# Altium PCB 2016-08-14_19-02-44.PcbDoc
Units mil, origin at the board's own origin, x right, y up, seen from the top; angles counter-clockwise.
Board outline 1900 x 2200 mil, 4 copper layers (Top Layer, MidLayer1, MidLayer2, Bottom Layer); 19 components, 10 nets, 41 pads, 48 vias.
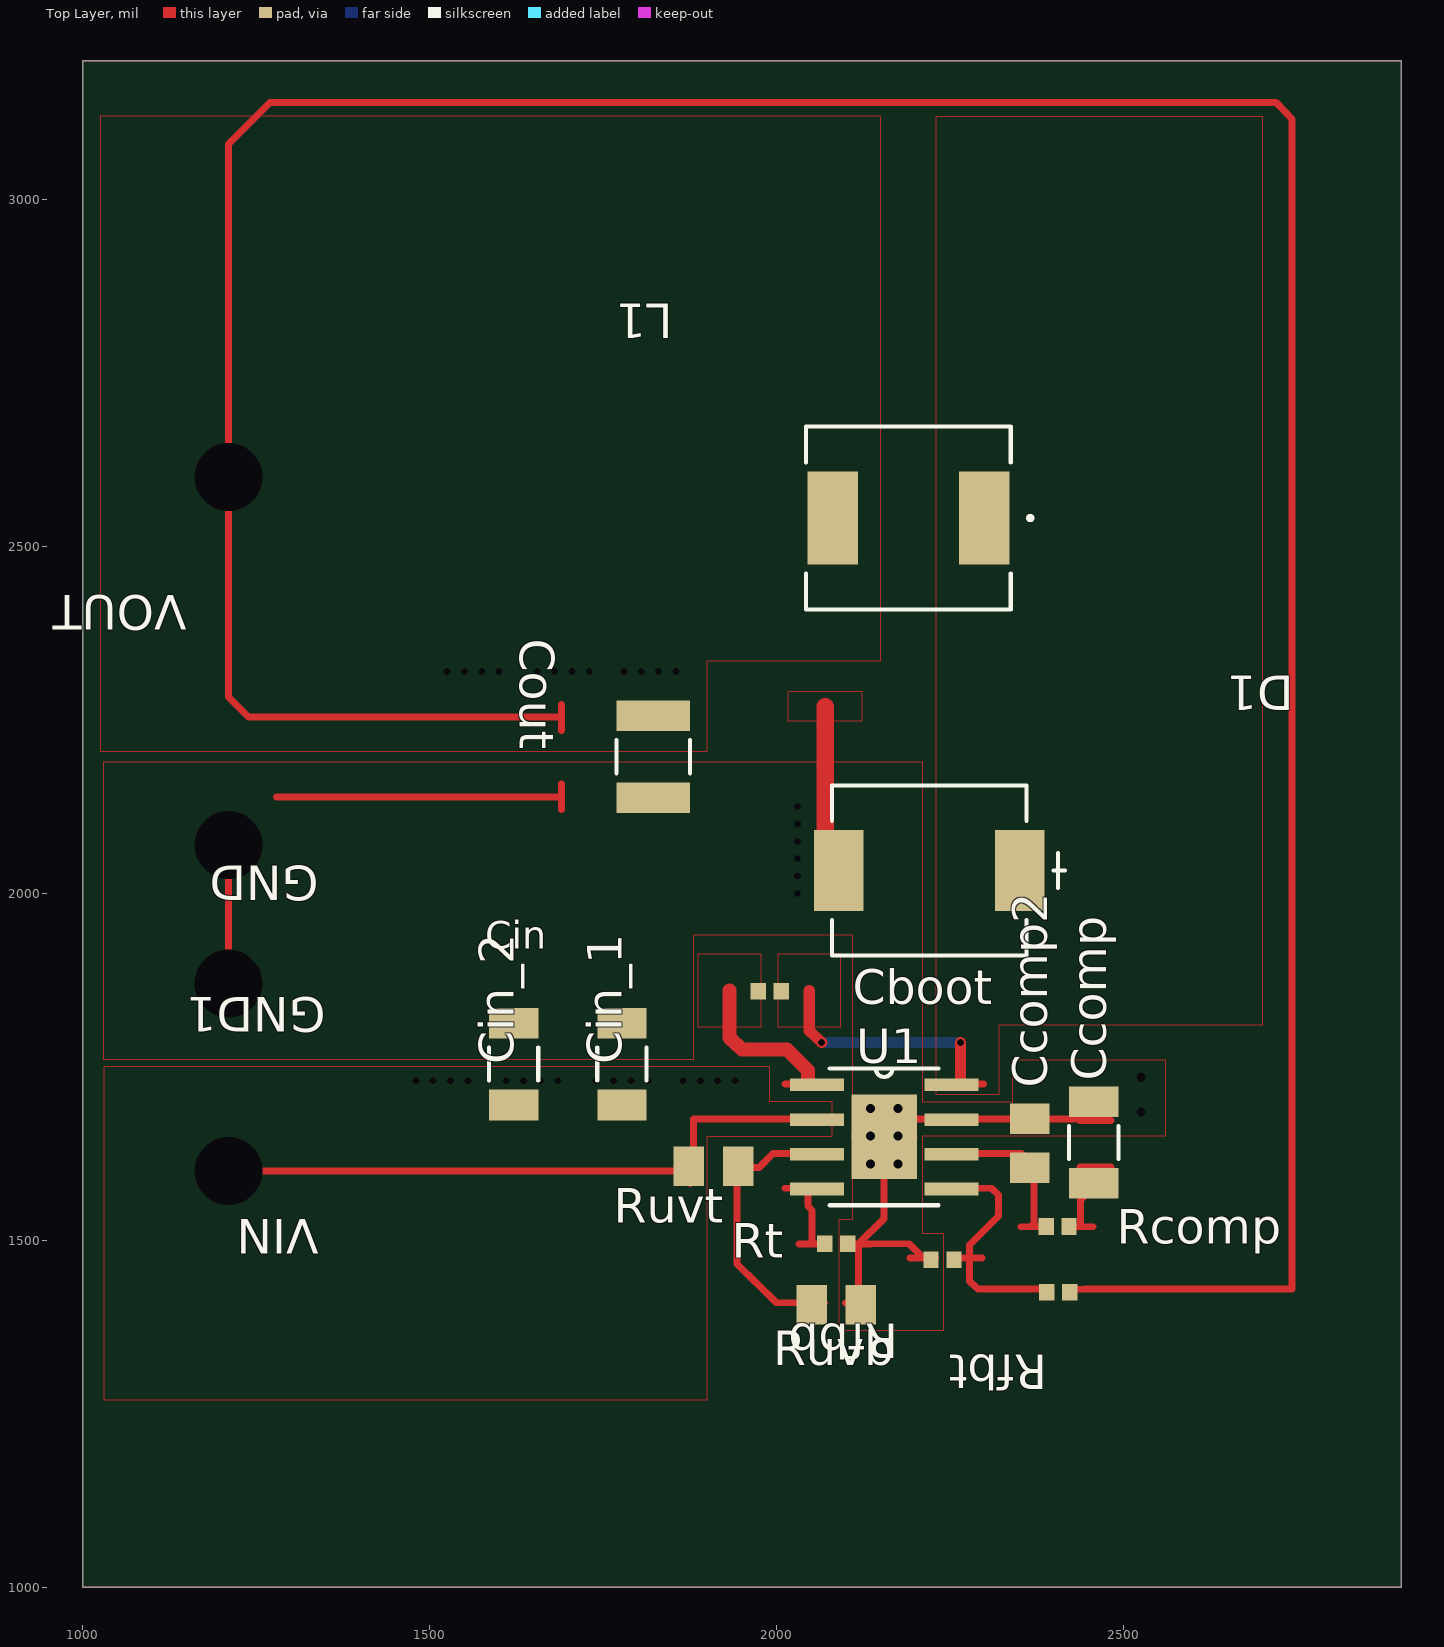
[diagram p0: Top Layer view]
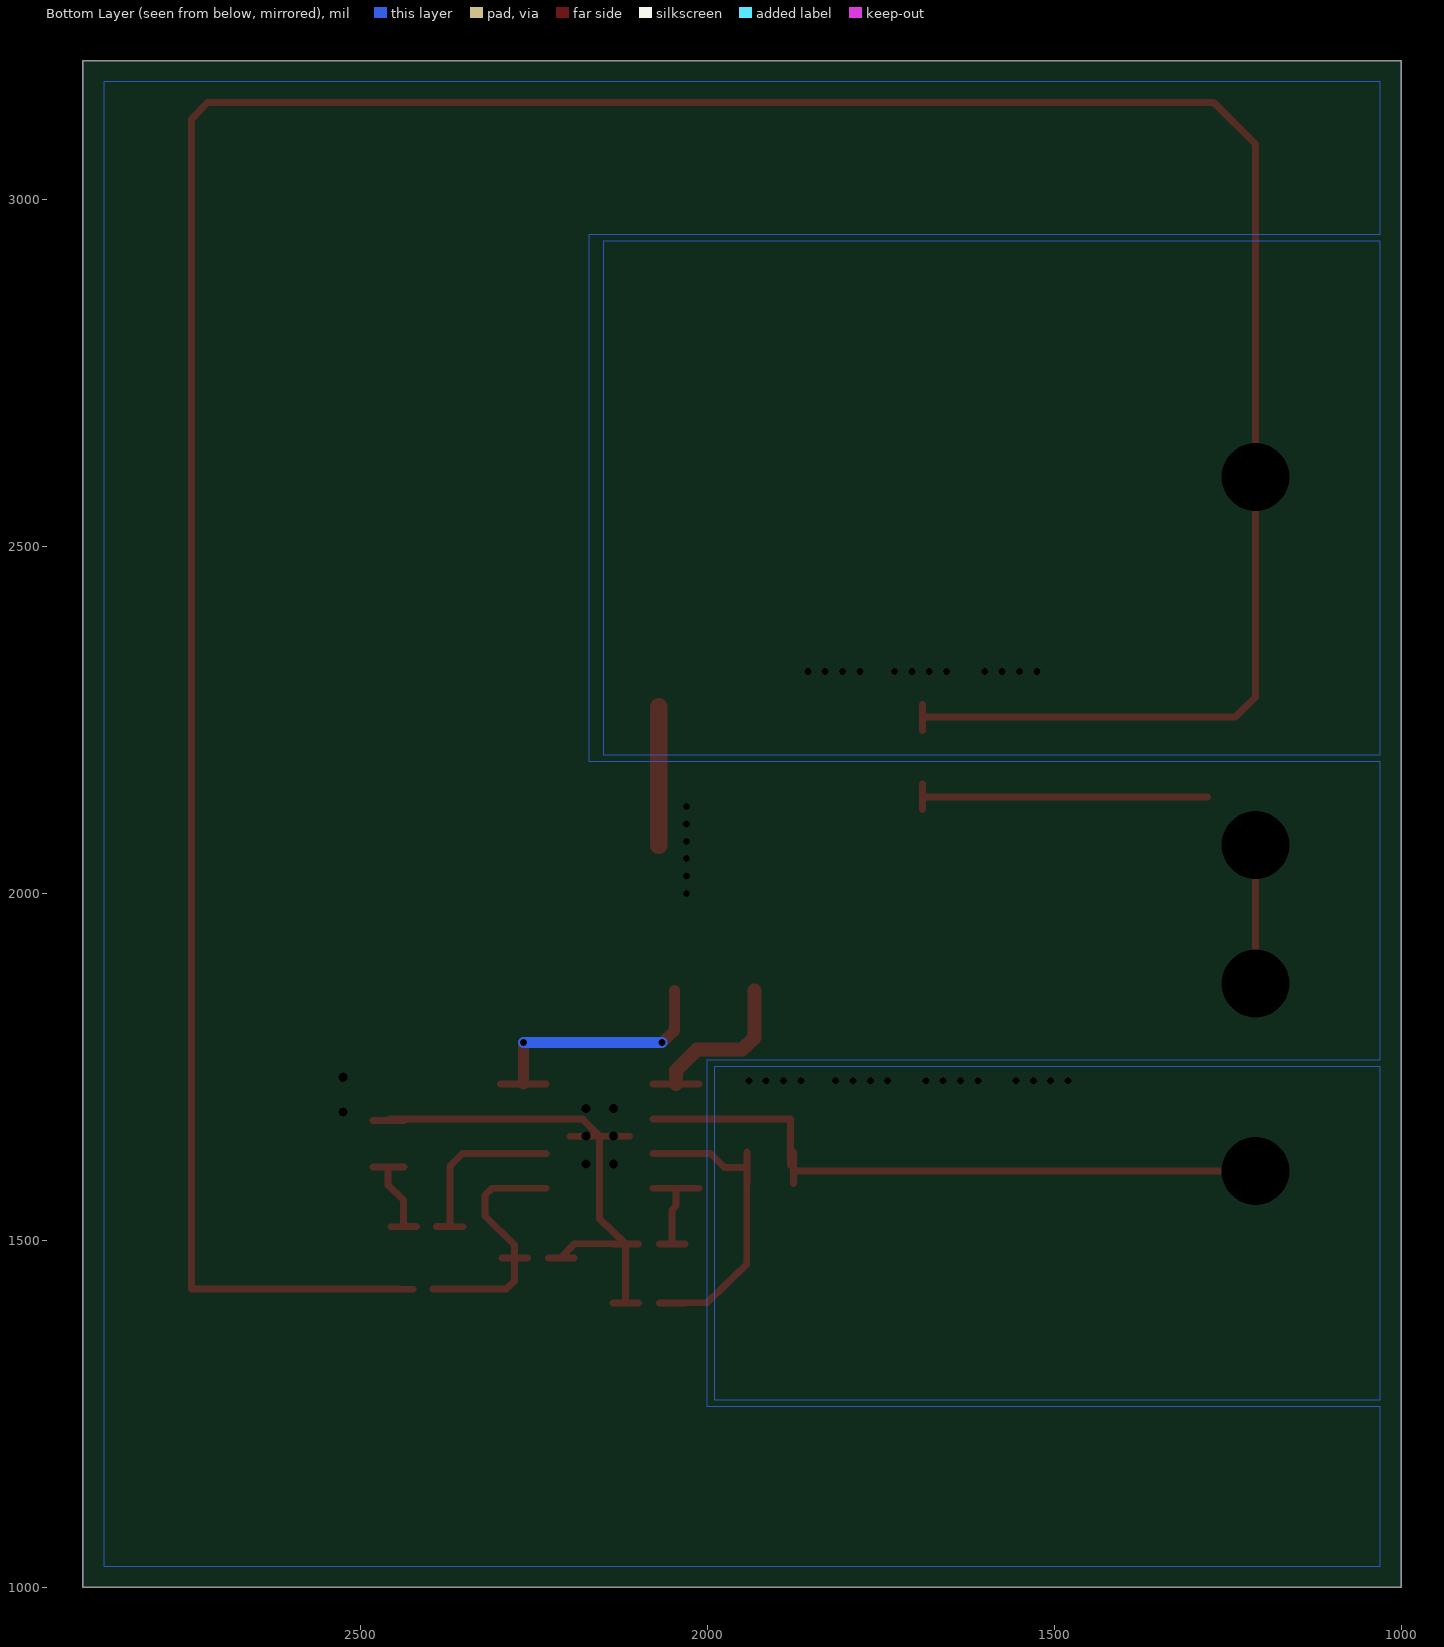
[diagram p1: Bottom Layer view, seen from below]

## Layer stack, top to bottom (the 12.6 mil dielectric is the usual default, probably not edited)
Top Layer: signal copper 1.4
Dielectric: core 12.6, FR-4, Dk 4.8
MidLayer1: signal copper 1.4
Dielectric: prepreg 12.6, FR-4, Dk 4.8
MidLayer2: signal copper 1.4
Dielectric: core 12.6, FR-4, Dk 4.8
Bottom Layer: signal copper 1.4

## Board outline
1000,1000 2900,1000 2900,3200 1000,3200

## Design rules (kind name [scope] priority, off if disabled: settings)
PlaneConnect [All] p0: scope1count=1 scope1_0_kind=Board scope1_0_value=Board scope2count=1 scope2_0_kind=Board scope2_0_value=Board commentlength=0 planeconnectstyle=Direct reliefexpansion=20 reliefentries=4 reliefconductorwidth=10 reliefairgap=10
PlaneConnect [All] p1: planeconnectstyle=Direct reliefexpansion=20 reliefentries=4 reliefconductorwidth=10 reliefairgap=10
PolygonConnect [All] p0: scope1count=1 scope1_0_kind=Board scope1_0_value=Board scope2count=1 scope2_0_kind=Board scope2_0_value=Board commentlength=0 connectstyle=Direct reliefconductorwidth=10 reliefentries=4 polygonreliefangle="90 Angle"
PolygonConnect [All] p1: connectstyle=Direct reliefconductorwidth=10 reliefentries=4 polygonreliefangle="90 Angle"

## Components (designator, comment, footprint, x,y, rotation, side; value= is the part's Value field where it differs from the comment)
Cboot "" 0402 1990,1859 r0 top
Ccomp "" 1206 2457,1641 r90 top
Ccomp2 "" 0805 2365,1640 r90 top
Cin_1 "" 1206 1777,1754 r90 top
Cin_2 "" 1206 1621,1754 r90 top
Cout "" 1210_280 1822,2197 r270 top
D1 "" SMC 2220,2033 r180 top
GND "" TP-1502 1209,2068 r180 top
GND1 "" TP-1502 1209,1870 r180 top
L1 "" SRP6540 2190,2541 r180 top
Rcomp "" 0402 2405,1520 r0 top
Rfbb "" 0402 2239,1472 r180 top
Rfbt "" 0402 2406,1425 r180 top
Rt "" 0402 2086,1495 r0 top
Ruvb "" 0805 2086,1407 r0 top
Ruvt "" 0805 1909,1607 r0 top
U1 "" R-PDSO-G8 2155,1649 r0 top
VIN "" TP-1502 1209,1599 r180 top
VOUT "" TP-1502 1209,2599 r180 top

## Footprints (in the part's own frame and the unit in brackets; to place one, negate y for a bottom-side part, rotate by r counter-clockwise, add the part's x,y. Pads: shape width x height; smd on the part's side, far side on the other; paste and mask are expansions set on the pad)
0402 [mil]
  rect 22x24 smd: 1(-16.5,0) 2(16.5,0)
0805 [mil]
  rect 44x57 smd: 1(-35.5,0) 2(35.5,0)
1206 [mil]
  rect 44x71 smd: 1(-59,0) 2(59,0)
  silkscreen extent -24,-36 24,36
1210_280 [mil]
  rect 44x106 smd: 1(-59,0) 2(59,0)
  silkscreen extent -24,-53 24,53
R-PDSO-G8 [mil]
  rect 78x18.14 smd: 1(-97,75) 2(-97,25) 3(-97,-25) 4(-97,-75) 5(97,-75) 6(97,-25) 7(97,25) 8(97,75)
  rect 94x122 smd: 9(0,0)
  silkscreen extent -78,-98 78,98
SMC [mil]
  rect 71x117 smd: 1(-130.5,0) 2(130.5,0)
  silkscreen extent -196,-123 140,123
SRP6540 [mil]
  rect 72.5x134 smd: 1(-109.25,0) 2(109.25,0)
  silkscreen extent -178,-132 148,132
TP-1502 [mil]
  round 65 / inner round 0 / far side round 65 hole 32: 1(0,0)

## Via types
v1: diameter 0, hole 10, Top Layer to Bottom Layer, 36 vias
v2: diameter 0, hole 13, Top Layer to Bottom Layer, 8 vias
v3: diameter 0, hole 98, Top Layer to Bottom Layer, 4 vias

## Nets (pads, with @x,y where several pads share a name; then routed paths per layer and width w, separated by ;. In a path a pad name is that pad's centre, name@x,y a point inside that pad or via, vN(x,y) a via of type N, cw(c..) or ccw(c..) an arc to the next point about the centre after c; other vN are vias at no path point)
0: Ccomp2.2 Ccomp.2 Cin_1.2 Cin_2.2 Cout.2 D1.2 GND1.1 GND.1 Rfbb.2 Rt.2 Ruvb.2 U1.7 U1.9 | length 1829.1
  Top Layer w10: v3(1210,1870) v3(1210,2070) ; 1279,2139 1690,2139 ; 1690,2121 1690,2158 ; 2099,1409.5 Ruvb.2@2136,1409.5 ; Rt.2@2099,1494.5 2136,1494.5 ; U1.9@2112,1650 U1.9@2198,1650 ; Ruvb.2@2118,1410 2118,1495 ; 2192,1474.5 Rfbb.2@2229,1474.5 ; 2211,1475 2191,1495 2118,1495 ; U1.7@2232,1675 2298,1675 ; 2437,1672.5 2482,1672.5 ; 2460,1673 2458,1675 2265,1675 2180,1675 2155,1650 2155,1531 2118,1495
  Top Layer w25: D1.2@2070,2069 2070,2269
  other v1: 2030,2000 2030,2025 2030,2050 2030,2075 2030,2100 2030,2125
  other v2: 2135,1610 2175,1610 2135,1650 2175,1650 2525,1685 2135,1690 2175,1690 2525,1735
1: Cboot.1 U1.1 | length 286.2
  Top Layer w10: 2012,1725 U1.1@2078,1725
  Top Layer w20: 1932,1860 1932,1792 1950,1775 2015,1775 2045,1745 U1.1@2045,1725
2: Cin_1.1 Cin_2.1 Ruvt.1 U1.2 VIN.1 | length 1016.1
  Top Layer w10: v3(1210,1600) 1871,1600 1876,1605 1880,1608 1880,1675 U1.2@2045,1675 ; Ruvt.1@1875.5,1582 Ruvt.1@1875.5,1627 ; 2012,1675 U1.2@2078,1675
  other v1: 1480,1730 1505,1730 1530,1730 1555,1730 1610,1730 1635,1730 1660,1730 1685,1730 1740,1730 1765,1730 1790,1730 1815,1730 1865,1730 1890,1730 1915,1730 1940,1730
3: Ccomp2.1 Rcomp.1 U1.6 | length 325.6
  Top Layer w10: U1.6@2232,1625 2298,1625 ; U1.6@2265,1625 2353,1625 2370,1608 2370,1606 Ccomp2.1@2370,1605 ; 2352,1519.5 Rcomp.1@2389,1519.5 ; 2366,1520 2369,1522 ; Ccomp2.1@2371,1605 2371,1520 Rcomp.1@2390,1520
4: Rt.1 U1.4 | length 185.2
  Top Layer w10: 2012,1575 U1.4@2078,1575 ; 2032,1494.5 Rt.1@2069,1494.5 ; U1.4@2045,1575 2045,1550 2051,1543 2051,1495
6: Rfbb.1 Rfbt.2 U1.5 | length 461.8
  Top Layer w10: U1.5@2232,1575 2298,1575 ; Rfbb.1@2259,1474.5 2296,1474.5 ; U1.5@2265,1575 2310,1575 2320,1565 2320,1535 2278,1493 2278,1475 2278,1441 2290,1430 2376,1430 Rfbt.2@2395,1430 ; 2357,1429.5 Rfbt.2@2394,1429.5
7: Cboot.2 D1.1 L1.1 U1.8 | length 408.8
  Top Layer w10: U1.8@2232,1725 2298,1725
  Top Layer w16: 2047,1860 2047,1802 v1(2065,1785) ; U1.8@2265,1725 v1(2265,1785)
  Bottom Layer w16: v1(2065,1785) v1(2265,1785)
8: Cout.1 L1.2 Rfbt.1 VOUT.1 | length 4917.1
  Top Layer w10: 1690,2235 1690,2272 ; 1690,2254 1239,2254 1210,2283 v3(1210,2600) 1210,3080 1270,3140 2720,3140 2743,3116 2743,1430 2443,1430 ; Rfbt.1@2424,1429.5 2461,1429.5
  other v1: 1525,2320 1550,2320 1575,2320 1600,2320 1655,2320 1680,2320 1705,2320 1730,2320 1780,2320 1805,2320 1830,2320 1855,2320
9: Ccomp.1 Rcomp.2 | length 195.1
  Top Layer w10: Rcomp.2@2419,1519.5 2456,1519.5 ; Rcomp.2@2420,1520 2438,1520 2438,1558 2460,1580 2460,1606 ; 2437,1605.5 2482,1605.5
18: Ruvb.1 Ruvt.2 U1.3 | length 528.2
  Top Layer w10: Ruvt.2@1942.5,1582 Ruvt.2@1942.5,1627 ; 2012,1625 U1.3@2078,1625 ; Ruvb.1@2032,1409.5 Ruvb.1@2069,1409.5 ; U1.3@2045,1625 1995,1625 1975,1605 1943,1605 1943,1466 2000,1410 Ruvb.1@2051,1410

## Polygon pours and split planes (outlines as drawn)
1 on Top Layer " " (solid, pour order 0): 1887,1807 1887,1913 1977,1913 1977,1807
7 on Top Layer " " (solid, pour order 1): 2002,1807 2002,1913 2092,1913 2092,1807
8 on Top Layer " " (solid, pour order 2): 1025,2205 1900,2205 1900,2335 2150,2335 2150,3120 1025,3120
2 on Top Layer " " (solid, pour order 3): 1030,1270 1900,1270 1900,1650 2080,1650 2080,1700 1990,1700 1990,1750 1030,1750
7 on Top Layer " " (solid, pour order 4): 2230,1710 2230,3120 2700,3120 2700,1810 2320,1810 2320,1710
0 on Top Layer " " (solid, pour order 7): 2017,2248 2017,2291 2123,2291 2123,2248
0 on Top Layer " " (solid, pour order 8): 1030,2190 2210,2190 2210,1700 2340,1700 2340,1760 2560,1760 2560,1650 2210,1650 2210,1510 2240,1510 2240,1370 2090,1370 2090,1530 2110,1530 2110,1940 1880,1940 1880,1760 1030,1760
2 on Bottom Layer " " (solid, pour order 5): 1030,1750 1990,1750 1990,1270 1030,1270
8 on Bottom Layer " " (solid, pour order 6): 1030,2940 2150,2940 2150,2200 1030,2200
0 on Bottom Layer " " (solid, pour order 9): 1030,1030 1030,1260 2000,1260 2000,1760 1030,1760 1030,2190 2170,2190 2170,2950 1030,2950 1030,3170 2870,3170 2870,1030
0 on MidLayer1 " " (solid, pour order 10): 1000,1000 1000,3200 2900,3200 2900,1000
0 on MidLayer2 " " (solid, pour order 11): 1000,1000 1000,3200 2900,3200 2900,1000

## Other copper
Multi-Layer:
  the board outline again, w1

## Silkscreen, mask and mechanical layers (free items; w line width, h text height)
Top Overlay:
  text "Cin" at 1580,1920 h40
